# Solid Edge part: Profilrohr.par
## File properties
Username: ahadarics
Dokumentum tartalom típus: 0
Author: ahadarics
Last saved by: ahadarics
Revision: 82
Sűrűség: 0,000 kg/m^3
Pontosság: 0,990
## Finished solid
Body 1: solid body, 6 faces, 6 edges, 0 vertices.
  Faces by surface: cone 2, cylinder 2, plane 2
  Edges by curve: circle 6
Bounding box of the edges (mm): 26.500 x 26.500 x 193.000, from (-13.25, -13.25, -171.5) to (13.25, 13.25, 21.5).
Cylindrical faces by radius (mm): R12.5 x1, R13.25 x1
Conical faces (half-angle, radius in mm at the cone's reference point): 15 deg R12.567 x2
Planar faces by outward normal: +z 1, -z 1
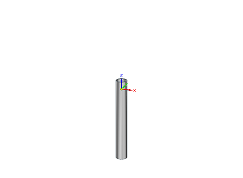
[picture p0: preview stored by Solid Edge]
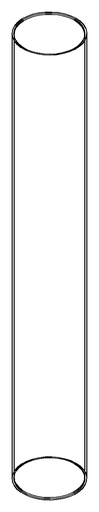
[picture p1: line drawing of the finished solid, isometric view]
